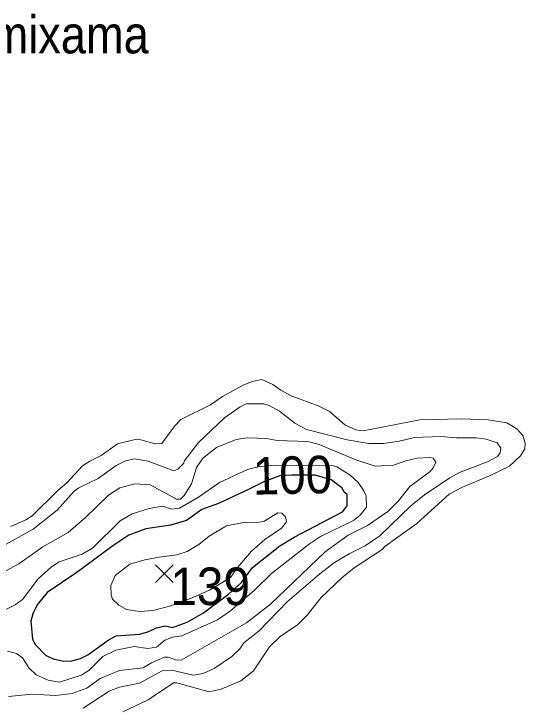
# Model space of a CAD drawing. Extents: x 474.5 to 500, y 7345.7 to 7373.4.
# Drawn here: x 475.736 to 476.825, y 7363.154 to 7364.627 of the extents above; entities that cross this region are included whole.
import ezdxf
from ezdxf.enums import TextEntityAlignment as Align

# ---------------------------------------------------------------- set-up
doc = ezdxf.new("R2010")
doc.units = 0
doc.header["$LTSCALE"] = 0.032
for name, color, linetype, lineweight in [('1', 7, 'Continuous', 25), ('2', 7, 'Continuous', 13), ('21', 7, 'Continuous', 25)]:
    doc.layers.add(name, color=color, linetype=linetype, lineweight=lineweight)
doc.layers.add('61', color=7, linetype='Continuous')

msp = doc.modelspace()

# ---------------------------------------------------------------- linework, layer by layer
at = {"layer": '1'}
msp.add_lwpolyline([(476.2373, 7363.6146), (476.1719, 7363.5841), (476.1361, 7363.571), (476.1036, 7363.5473), (476.0693, 7363.5376), (476.0167, 7363.5296), (475.9811, 7363.5166), (475.9465, 7363.4938), (475.8699, 7363.4364), (475.8072, 7363.3944), (475.7857, 7363.3679), (475.7764, 7363.3487), (475.7724, 7363.3328), (475.7755, 7363.2945), (475.7823, 7363.2825), (475.8038, 7363.2606), (475.8195, 7363.253), (475.8422, 7363.248), (475.8597, 7363.2487), (475.8779, 7363.2537), (475.8933, 7363.2614), (475.9369, 7363.2928), (475.9537, 7363.3019), (476.0039, 7363.3054), (476.0215, 7363.3103), (476.0394, 7363.3191), (476.0581, 7363.323), (476.0741, 7363.3198), (476.1052, 7363.3307), (476.1399, 7363.351), (476.1927, 7363.3904), (476.2207, 7363.4152), (476.2439, 7363.4474), (476.302, 7363.4936), (476.3326, 7363.5122), (476.4356, 7363.566), (476.4456, 7363.5791), (476.4456, 7363.6027), (476.4401, 7363.607), (476.4342, 7363.6175), (476.4113, 7363.634), (476.3777, 7363.6444), (476.3281, 7363.6443), (476.3026, 7363.6427), (476.2695, 7363.6306)], close=True, dxfattribs=at)
at = {"layer": '2'}
for points in [[(475.7295, 7363.5345), (475.7628, 7363.5495), (475.7752, 7363.5576), (475.8288, 7363.6108), (475.8497, 7363.6285), (475.8821, 7363.6639), (475.8975, 7363.6743), (475.9221, 7363.6858), (475.9566, 7363.7108), (475.9945, 7363.7203), (476.0063, 7363.7195), (476.0369, 7363.7107), (476.0512, 7363.7115), (476.0779, 7363.7485), (476.0912, 7363.7629), (476.155, 7363.7943), (476.1805, 7363.8118), (476.2239, 7363.8359), (476.2435, 7363.844), (476.2641, 7363.8479), (476.2871, 7363.8377), (476.3041, 7363.8252), (476.3267, 7363.8131), (476.3837, 7363.7919), (476.4073, 7363.7808), (476.4403, 7363.7517), (476.4641, 7363.7406), (476.4799, 7363.7386), (476.6001, 7363.7617), (476.6892, 7363.7641), (476.7458, 7363.7617), (476.7852, 7363.7554), (476.807, 7363.7432), (476.8196, 7363.729), (476.8245, 7363.7122), (476.8237, 7363.7005), (476.8149, 7363.6852), (476.791, 7363.6633), (476.7485, 7363.6427), (476.6908, 7363.6187), (476.6625, 7363.6036), (476.5937, 7363.5409), (476.5259, 7363.4923), (476.5198, 7363.4857), (476.4607, 7363.4468), (476.434, 7363.4255), (476.3905, 7363.3835), (476.3606, 7363.3457), (476.3397, 7363.3255), (476.3029, 7363.3), (476.2806, 7363.2784), (476.2464, 7363.2269), (476.2192, 7363.2058), (476.1773, 7363.1881), (476.1521, 7363.1826), (476.0832, 7363.2015), (476.0757, 7363.2016), (476.0218, 7363.1652), (475.9683, 7363.1401)], [(475.7131, 7363.4938), (475.7769, 7363.5294), (475.8285, 7363.5698), (475.8643, 7363.6103), (475.8742, 7363.6172), (475.9154, 7363.6369), (475.9536, 7363.6644), (475.974, 7363.6747), (475.9928, 7363.6787), (476.0223, 7363.6741), (476.0764, 7363.6534), (476.0849, 7363.6567), (476.0977, 7363.67), (476.0989, 7363.6743), (476.1289, 7363.7138), (476.1845, 7363.7662), (476.2175, 7363.7897), (476.2306, 7363.796), (476.2685, 7363.796), (476.2796, 7363.7928), (476.3018, 7363.7802), (476.3339, 7363.7548), (476.3588, 7363.7414), (476.4455, 7363.7191), (476.4916, 7363.7115), (476.5228, 7363.7115), (476.556, 7363.7163), (476.5886, 7363.7242), (476.645, 7363.7267), (476.6784, 7363.7235), (476.7206, 7363.7234), (476.7413, 7363.7209), (476.7646, 7363.713), (476.7726, 7363.7016), (476.7713, 7363.6914), (476.7659, 7363.6837), (476.7444, 7363.6722), (476.6863, 7363.6507), (476.664, 7363.6387), (476.6102, 7363.6023), (476.581, 7363.5788), (476.5152, 7363.5148), (476.4837, 7363.4935), (476.4502, 7363.4768), (476.4186, 7363.4577), (476.3876, 7363.4342), (476.3181, 7363.3741), (476.2579, 7363.3115), (476.2256, 7363.2865), (476.2173, 7363.2743), (476.2001, 7363.2577), (476.1622, 7363.2322), (476.139, 7363.2216), (476.1176, 7363.2177), (476.0725, 7363.2288), (476.0516, 7363.2272), (476.0036, 7363.201), (475.9608, 7363.1922), (475.9392, 7363.1838), (475.8838, 7363.1473)], [(475.725, 7363.1722), (475.7745, 7363.1778), (475.8258, 7363.1746), (475.8603, 7363.1786), (475.8914, 7363.1903), (475.9199, 7363.2108), (475.9608, 7363.2281), (476.0112, 7363.2334), (476.029, 7363.2445), (476.0569, 7363.256), (476.0649, 7363.2566), (476.0805, 7363.2503), (476.0922, 7363.2496), (476.2315, 7363.3298), (476.2822, 7363.3694), (476.399, 7363.4805), (476.4476, 7363.516), (476.4889, 7363.5369), (476.5325, 7363.567), (476.5547, 7363.5891), (476.5793, 7363.6201), (476.6221, 7363.6518), (476.6288, 7363.6598), (476.6344, 7363.6718), (476.6287, 7363.6804), (476.6206, 7363.6819), (476.5948, 7363.6803), (476.5703, 7363.6748), (476.5443, 7363.6651), (476.5055, 7363.6634), (476.4639, 7363.6767), (476.3858, 7363.7095), (476.3613, 7363.7162), (476.2967, 7363.7179), (476.2736, 7363.7226), (476.2329, 7363.7234), (476.2092, 7363.7202), (476.1675, 7363.7028), (476.1386, 7363.6805), (476.125, 7363.6602), (476.1144, 7363.6258), (476.0989, 7363.601), (476.0907, 7363.5928), (476.0821, 7363.5933), (476.0266, 7363.6238), (475.9938, 7363.626), (475.9614, 7363.6169), (475.9378, 7363.6018), (475.8889, 7363.5536), (475.8516, 7363.522), (475.7976, 7363.4911), (475.7468, 7363.455), (475.7193, 7363.4401)], [(475.6935, 7363.3461), (475.7391, 7363.3681), (475.7543, 7363.3792), (475.7882, 7363.4235), (475.8164, 7363.4491), (475.8326, 7363.4596), (475.8817, 7363.4757), (475.9035, 7363.4885), (475.9621, 7363.5471), (475.9883, 7363.5616), (476.0244, 7363.5734), (476.0528, 7363.5781), (476.0718, 7363.5719), (476.0884, 7363.5735), (476.1289, 7363.5976), (476.174, 7363.6287), (476.2332, 7363.6563), (476.2564, 7363.6618), (476.2923, 7363.6656), (476.4164, 7363.6642), (476.4236, 7363.662), (476.4518, 7363.6438), (476.4689, 7363.6282), (476.4814, 7363.6111), (476.4864, 7363.6003), (476.4871, 7363.5761), (476.4731, 7363.5586), (476.4591, 7363.5474), (476.3886, 7363.5131), (476.3651, 7363.4978), (476.2845, 7363.4346), (476.2484, 7363.3994), (476.197, 7363.3548), (476.1694, 7363.3356), (476.0936, 7363.3016), (476.0741, 7363.2991), (476.0572, 7363.2926), (476.0397, 7363.2773), (476.021, 7363.2751), (475.992, 7363.279), (475.9533, 7363.2715), (475.9257, 7363.2577), (475.8956, 7363.2276), (475.8791, 7363.2176), (475.8332, 7363.2033), (475.8088, 7363.2073), (475.7838, 7363.2184), (475.7688, 7363.2325), (475.7543, 7363.2547), (475.742, 7363.2639), (475.7223, 7363.2688)]]:
    msp.add_lwpolyline(points, dxfattribs=at)
msp.add_lwpolyline([(476.0702, 7363.3658), (476.1119, 7363.3811), (476.1525, 7363.3994), (476.1976, 7363.426), (476.2125, 7363.4476), (476.2418, 7363.4821), (476.2701, 7363.5067), (476.306, 7363.5314), (476.3163, 7363.545), (476.3147, 7363.5557), (476.3068, 7363.5629), (476.2981, 7363.5637), (476.268, 7363.5454), (476.2534, 7363.5432), (476.2284, 7363.5439), (476.1888, 7363.5359), (476.1521, 7363.5144), (476.1301, 7363.4965), (476.1052, 7363.4814), (476.0829, 7363.4742), (476.0454, 7363.4697), (476.015, 7363.464), (475.9827, 7363.4544), (475.9516, 7363.4303), (475.9426, 7363.4087), (475.9429, 7363.3892), (475.9464, 7363.3799), (475.9593, 7363.3669), (475.9757, 7363.3576), (476.0034, 7363.3533), (476.0326, 7363.3557)], close=True, dxfattribs=at)
at = {"layer": '21'}
for p, q in [((476.0374, 7363.4532), (476.0749, 7363.4157)), ((476.0749, 7363.4532), (476.0374, 7363.4157))]:
    msp.add_line(p, q, dxfattribs=at)

# ---------------------------------------------------------------- texts
at = {"layer": '61'}
for s, width, p in [('Pr. da Guamixama', 0.9, (475.6221, 7364.543)), ('139', 0.95, (476.154, 7363.3673))]:
    msp.add_text(s, height=0.08, dxfattribs=dict(at, width=width)).set_placement(p, align=Align.CENTER)
at = {"layer": '61', "width": 0.95}
msp.add_text('100', height=0.08, rotation=1.242, dxfattribs=at).set_placement((476.3299, 7363.6043), align=Align.CENTER)

doc.saveas('drawing.dxf')
